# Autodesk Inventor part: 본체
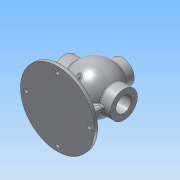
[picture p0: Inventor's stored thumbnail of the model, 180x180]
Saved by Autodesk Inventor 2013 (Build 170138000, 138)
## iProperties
Created: 2020-08
Part Number: 본체
Material: 알루미늄 6061
Document SubType Name: Modeling
Designer: 88
Density: 2.71 g/cm^3
Mass: 1759.17 g
Surface Area: 1342.58 cm^2
Volume: 649.139 cm^3
Author: 88
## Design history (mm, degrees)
sketch "스케치3"
  geometry: L1 (-68, 0)-(68, 0); L2 (-68, 0)-(-68, 17.5); L3 (-68, 31)-(-42.988, 31); L4 (68, 0)-(68, 17.5); L5 (68, 31)-(42.988, 31); L6 (-52, 17.5)-(-52, 18.5); L7 (-52, 18.5)-(-50.25, 18.5); L8 (-50.25, 18.5)-(-50.25, 17.5); L9 (-50.25, 17.5)-(-39.278, 17.5); L10 (-52, 17.5)-(-68.035, 17.5); L11 (39.278, 17.5)-(68, 17.5); L12 (-68, 17.5)-(-68, 31); L13 (68, 17.5)-(68, 31); A1 r 53 centre (0, 0) between (42.988, 31) and (-42.988, 31); A2 r 43 centre (0, 0) between (39.278, 17.5) and (-39.278, 17.5); 2 further points
  constraints: 26 end point, 10 perpendicular, 4 point on circle, 3 coincident, 2 centre point, 2 horizontal, 1 collinear, 1 midpoint, 1 parallel, 1 point on line
  dimensions: "d0" = 53 radius of A1; "d1" = 43 radius of A2; "d2" = 136 distance of L1.start L1.end; "d3" = 62 diameter of L3 L1; "d4" = 62 diameter of L5 L1; "d5" = 37 diameter of L7 L1; "d6" = 1.75 distance of L6.end L7.end; "d13" = 35 diameter of L10 L1; "d14" = 35 diameter of L11 L1; "d15" = 16 distance between parallel lines of L2 L6
revolve "회전1" sketch "스케치3" stored, may be unused: angle "d16" = 90 deg
node "작업 평면1"
sketch "스케치4"
  geometry: C1 r 85 at (0, 0); 1 further point
  constraints: 1 centre point, 1 coincident
  dimensions: "d18" = 170 diameter of C1
extrude "돌출1" join sketch "스케치4" distance "d19" = 10; taper "d20" = 0 deg
sketch "스케치12"
  geometry: L1 (4, 43)-(-4, 43); L2 (-4, 43)-(-4, -43); L3 (-4, -43)-(4, -43); L4 (4, -43)-(4, 43); L5 (4, 43)-(-4, -43); L6 (-4, 43)-(4, -43); L7 (52, 4)-(-52, 4); L8 (-52, 4)-(-52, -4); L9 (-52, -4)-(52, -4); L10 (52, -4)-(52, 4); L11 (52, 4)-(-52, -4); L12 (-52, 4)-(52, -4); C1 r 85 at (0, 0) reference
  constraints: 24 end point, 4 midpoint, 4 parallel, 2 horizontal, 2 perpendicular
  dimensions: "d76" = 8 distance of L3.end L2.end; "d77" = 86 distance of L2.end L1.end; "d78" = 104 distance of L9.end L8.end; "d79" = 8 distance of L8.end L7.end
extrude "돌출5" join sketch "스케치12" stored distance "d80" = 52.75; taper "d81" = 0 deg
node "작업 평면2"
sketch "스케치6"
  geometry: C1 r 27 at (0, 0); 1 further point
  constraints: 1 centre point, 1 coincident
  dimensions: "d28" = 54 diameter of C1
extrude "돌출3" join sketch "스케치6" stored distance "d29" = 10; taper "d30" = 0 deg
sketch "스케치7"
  geometry: C1 r 27 at (0, 0) reference; C2 r 13 at (0, 0)
  constraints: 1 centre point, 1 coincident
  dimensions: "d31" = 26 diameter of C2
extrude "돌출4" cut sketch "스케치7" distance "d32" = 52.75; taper "d33" = 0 deg
sketch "스케치8"
  geometry: C1 r 13 at (0, 0) reference; 1 further point
  constraints: 1 vertical alignment
  dimensions: "d34" = 20 distance of C1.centre point (0, 20)
hole "구멍1" sketch "스케치8" at (0, 20) diameter "d35" = 3.242; stored, may be unused: countersink angle "d39" = 90 deg, drill point angle "d41" = 118 deg; dims "d36" = 12, "d37" = 4, "d38" = 2, "d40" = 15
sketch "스케치9"
  geometry: C1 r 31 at (0, 0) reference; 1 further point
  constraints: 1 vertical alignment
  dimensions: "d45" = 24 distance of C1.centre point (0, 24)
hole "구멍2" sketch "스케치9" at (0, 24) diameter "d46" = 3.242; stored, may be unused: countersink angle "d50" = 90 deg, drill point angle "d52" = 118 deg; dims "d47" = 12, "d48" = 4, "d49" = 2, "d51" = 15
node "작업 평면3"
sketch "스케치10"
  geometry: L1 (-27, 0)-(27, 0) reference; L2 (-27, 0)-(-27, -19.393) reference; 2 further points
  constraints: 1 other
  dimensions: "d56" = 9 distance from line of L1 point (0, -9); "d57" = 27 distance from line of L2 point (0, -9)
feature "엠보싱1" sketch "스케치10" dims "d0" = 53, "d1" = 43, "d2" = 136, "d3" = 62, "d4" = 62, "d5" = 37, "d6" = 1.75, "d13" = 35, "d14" = 35, "d15" = 16, "d20" = 0, "d58" = 0.5, "d59" = 0
sketch "스케치11"
  geometry: C1 r 85 at (0, 0) reference; 1 further point
  constraints: 1 vertical alignment
  dimensions: "d60" = 72.5 distance of point (0, 72.5) C1.centre
hole "구멍3" sketch "스케치11" at (0, 72.5) diameter "d61" = 9; stored, may be unused: countersink angle "d65" = 90 deg, drill point angle "d67" = 118 deg; dims "d62" = 12, "d63" = 4, "d64" = 2, "d66" = 15
fillet "모깎기1" dims "d71" = 3
fillet "모깎기2" dims "d82" = 3
fillet "모깎기3" dims "d83" = 3
fillet "모깎기4" dims "d84" = 3
chamfer "모따기1" distance "d85" = 1; stored, may be unused: second distance "d86" = 2, angle "d87" = 45 deg
chamfer "모따기2" distance "d88" = 1; stored, may be unused: second distance "d89" = 2, angle "d90" = 45 deg
node "솔리드1"
pattern_circular "원형 패턴1" dims angle "d43" = 360 deg
pattern_circular "원형 패턴2" dims angle "d54" = 360 deg
mirror "대칭1"
pattern_circular "원형 패턴3" dims angle "d69" = 360 deg
other parameters: "d17" = -85
